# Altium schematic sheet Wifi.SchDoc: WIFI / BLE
size A4; Author: Silvio Navaretti; CompanyName: Arduino srl; DocumentNumber: ABX00063; Revision: V1.2; SheetNumber: 6; SheetTotal: 8; RevAuthor: Silvio Navaretti
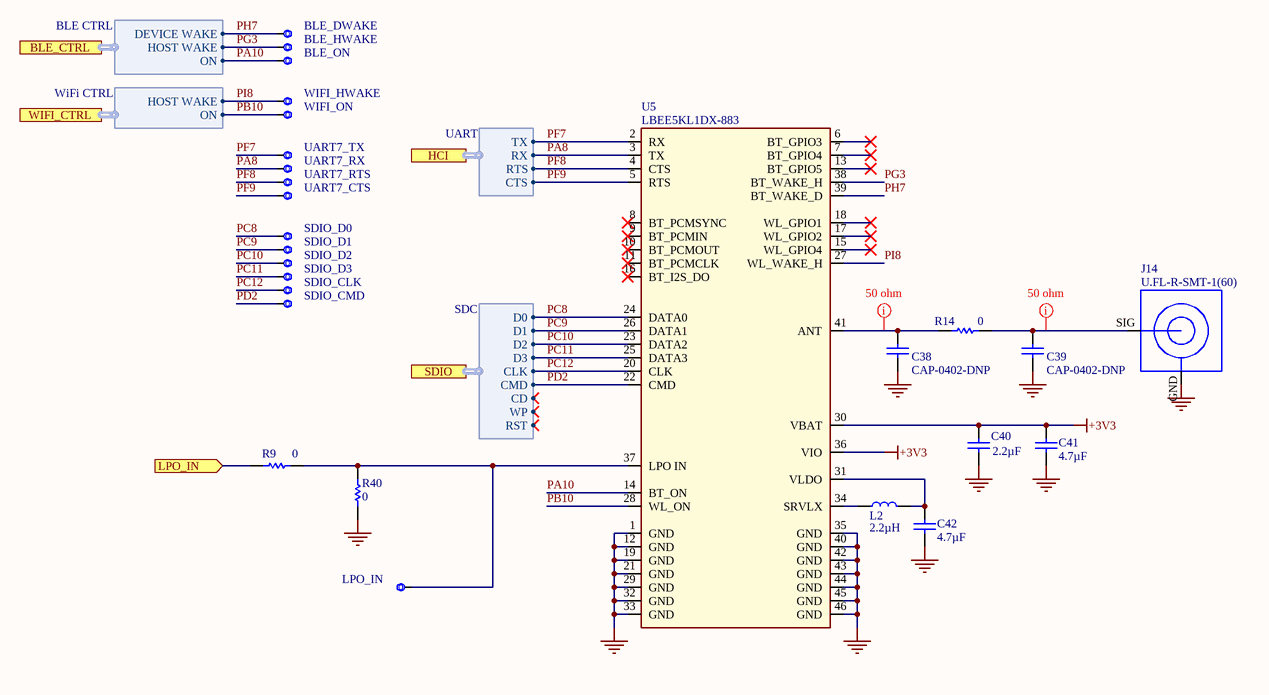
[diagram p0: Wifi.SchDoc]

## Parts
BLE_DWAKE  CMP-018-0005-A.3  [TP-1.00MM]  (value not drawn)  (no BOM)
BLE_HWAKE  CMP-018-0005-A.3  [TP-1.00MM]  (value not drawn)  (no BOM)
BLE_ON  CMP-018-0005-A.3  [TP-1.00MM]  (value not drawn)  (no BOM)
C38  CAP-0402-DNP  [CAP-0402]  (no BOM)
C39  CAP-0402-DNP  [CAP-0402]  (no BOM)
C40  value 2.2µF  [CAP-0402]  (hidden comment: GRM155R60J225KE95D)
C41  value 4.7µF  [CAP-0402]  (hidden comment: GRM155R60J475ME47D)
C42  value 4.7µF  [CAP-0402]  (hidden comment: GRM155R60J475ME47D)
J14  U.FL-R-SMT-1(60)  [U.FL-R-SMT-1(60)-1]
L2  value 2.2µH  [FP-LQM18PN_GH-IPC_C]  (hidden comment: LQM18PN2R2MGHD)
LPO_IN  CMP-018-0005-A.3  [TP-1.00MM]  (value not drawn)  (no BOM)
R9  value 0  [RES-0402]  (hidden comment: CRCW04020000Z0EDC)
R14  value 0  [RES-0402]  (hidden comment: CRCW04020000Z0EDC)
R40  value 0  [RES-0402]  (hidden comment: CRCW04020000Z0EDC)
SDIO_CLK  CMP-018-0005-A.3  [TP-1.00MM]  (value not drawn)  (no BOM)
SDIO_CMD  CMP-018-0005-A.3  [TP-1.00MM]  (value not drawn)  (no BOM)
SDIO_D0  CMP-018-0005-A.3  [TP-1.00MM]  (value not drawn)  (no BOM)
SDIO_D1  CMP-018-0005-A.3  [TP-1.00MM]  (value not drawn)  (no BOM)
SDIO_D2  CMP-018-0005-A.3  [TP-1.00MM]  (value not drawn)  (no BOM)
SDIO_D3  CMP-018-0005-A.3  [TP-1.00MM]  (value not drawn)  (no BOM)
U5  LBEE5KL1DX-883  [LBEE5KL1DX-883]
UART7_CTS  CMP-018-0005-A.3  [TP-1.00MM]  (value not drawn)  (no BOM)
UART7_RTS  CMP-018-0005-A.3  [TP-1.00MM]  (value not drawn)  (no BOM)
UART7_RX  CMP-018-0005-A.3  [TP-1.00MM]  (value not drawn)  (no BOM)
UART7_TX  CMP-018-0005-A.3  [TP-1.00MM]  (value not drawn)  (no BOM)
WIFI_HWAKE  CMP-018-0005-A.3  [TP-1.00MM]  (value not drawn)  (no BOM)
WIFI_ON  CMP-018-0005-A.3  [TP-1.00MM]  (value not drawn)  (no BOM)

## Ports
BLE_CTRL (harness BLE CTRL), HCI (harness UART), LPO_IN (in), SDIO (harness SDC), WIFI_CTRL (harness WiFi CTRL)

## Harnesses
BLE CTRL: HOST WAKE, DEVICE WAKE, ON
UART: RX, TX, RTS, CTS
WiFi CTRL: HOST WAKE, ON
SDC: CLK, CMD, D0, D1, D2, D3, CD, WP, RST

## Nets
+3V3: C40.2 C41.1 U5.30(VBAT) U5.36(VIO)
GND: C38.2 C39.2 C40.1 C41.2 C42.2 J14.GND R40.1 U5.1(GND) U5.12(GND) U5.19(GND) U5.21(GND) U5.29(GND) U5.32(GND) U5.33(GND) U5.35(GND) U5.40(GND) U5.42(GND) U5.43(GND) U5.44(GND) U5.45(GND) U5.46(GND)
LPO_IN: R9.1 ; port LPO_IN
PA8: U5.3(TX) UART7_RX.X ; port HCI.RX
PA10: BLE_ON.X U5.14(BT_ON) ; port BLE_CTRL.ON
PB10: U5.28(WL_ON) WIFI_ON.X ; port WIFI_CTRL.ON
PC8: SDIO_D0.X U5.24(DATA0) ; port SDIO.D0
PC9: SDIO_D1.X U5.26(DATA1) ; port SDIO.D1
PC10: SDIO_D2.X U5.23(DATA2) ; port SDIO.D2
PC11: SDIO_D3.X U5.25(DATA3) ; port SDIO.D3
PC12: SDIO_CLK.X U5.20(CLK) ; port SDIO.CLK
PD2: SDIO_CMD.X U5.22(CMD) ; port SDIO.CMD
PF7: U5.2(RX) UART7_TX.X ; port HCI.TX
PF8: U5.4(CTS) UART7_RTS.X ; port HCI.RTS
PF9: U5.5(RTS) UART7_CTS.X ; port HCI.CTS
PG3: BLE_HWAKE.X U5.38(BT_WAKE_H) ; port BLE_CTRL.HOST WAKE
PH7: BLE_DWAKE.X U5.39(BT_WAKE_D) ; port BLE_CTRL.DEVICE WAKE
PI8: U5.27(WL_WAKE_H) WIFI_HWAKE.X ; port WIFI_CTRL.HOST WAKE
NetC38_1: C38.1 R14.1 U5.41(ANT)
NetC39_1: C39.1 J14.SIG R14.2
NetC42_1: C42.1 L2.2 U5.31(VLDO)
NetL2_1: L2.1 U5.34(SRVLX)
NetLPO_IN_X: LPO_IN.X R9.2 R40.2 U5.37(LPO_IN)

Not connected (* = marked no-connect by the designer): U5 6(BT_GPIO3)* 7(BT_GPIO4)* 8(BT_PCMSYNC)* 9(BT_PCMIN)* 10(BT_PCMOUT)* 11(BT_PCMCLK)* 13(BT_GPIO5)* 15(WL_GPIO4)* 16(BT_I2S_DO)* 17(WL_GPIO2)* 18(WL_GPIO1)*

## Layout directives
net class 50 ohm: NetC38_1, NetC39_1

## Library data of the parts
BLE_DWAKE BLE_HWAKE BLE_ON LPO_IN SDIO_CLK SDIO_CMD SDIO_D0-SDIO_D3 UART7_CTS UART7_RTS UART7_RX UART7_TX WIFI_HWAKE WIFI_ON = UT0013-A.4: Test point 1.00mm
C38 C39 = UT0021-A.2: DNP CAP 0402
C40 = C0031-A.11: CAP CHIP 0402 2.2uF 6.3V X5R 10%; Manufacturer: Murata; Code Arduino: A5529
C41 C42 = C0037-A.11: CAP CHIP 0402 4.7uF 6V3 X5R 20%; Manufacturer: Murata; Code Arduino: 0833; Voltage: 6.3V
J14 = J0045-A.6: CONN Micro UFL; Manufacturer: Hirose; Code Arduino: A5364
L2 = I0051-A.4: IND FIXED SMD 0603 2.2uH, 20%,; Manufacturer: Murata; Code Arduino: I0051; Test Frequency: 1MHz; DC Resistance (DCR): 250mR
R9 R40 = R0000-A.15: RES CHIP 0402 0R 1/16W; Manufacturer: Vishay; Power: 63mW; Tolerance: J; Code Arduino: 0039
R14 = R0000-A.15: RES CHIP 0402 0R 1/16W; Manufacturer: Vishay; Code Arduino: 0039; Tolerance: J; Power: 63mW
U5 = U0008-A.14: MODULE WiFi 11b/g/n+BLUETOOTH 4.2 SHIELDED ULTRA SMALL LBEE5KL1DX; Manufacturer: Murata; Frequency: 2.4GHz; Device Type: IC; Code Arduino: U0008; Current - Receiving: 60mA; Current - Transmitting: 370mA; Data Rate: 65Mbps; Interface: UART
